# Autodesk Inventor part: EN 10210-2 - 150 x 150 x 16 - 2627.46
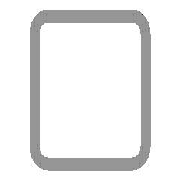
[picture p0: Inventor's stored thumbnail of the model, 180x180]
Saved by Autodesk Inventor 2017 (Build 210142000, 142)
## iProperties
Created: 2016-02
Part Number: EN 10210-2 - 150 x 150 x 16 - 2627.46
Material: Steel, Mild
Description: Tube
Document SubType Name: Modeling
Standard: DIN
Designer: iusti
Standard Revision: 2006-07
Standards Organization: DIN
Language: en-US
Size Designation: 150 x 150 x 16
Categories: <MemberInstance><Categories><Category DisplayName="Structural Shapes" InternalName="089c4875-fa83-4c05-b084-43b9cc11f5ed" Mnemonic="GRDR"><CategoryParameter Dis
Stock Number: 150 x 150 x 16
Density: 7.85 g/cm^3
Appearance: Semi-Polished
IsCustomPart: 1
_CCFamilyMember: 70
_CCFamilyDisplayName: DIN EN 10210-2 (Square) - Tube — Sizes in parentheses have been withdrawn
_FrameMemberDoc: Frame Member File
_Version: 15.0.0
_GetPNFromCC: 1
Author: iusti
G_L: 2627.460 mm
G_W: 150.000 mm
G_H: 150.000 mm
+AC2412DF-FBE4-4A06-B88A-D7E3DE0B8CAC+CUTDETAIL1: Cut
+05A7F50A-9806-4571-A7E4-6AEFE63C232C+CUTDETAIL2: Cut
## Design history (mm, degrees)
node "Start plane"
node "End plane"
sketch "Sketch"
  geometry: L1 (-75, -51)-(-75, 51); L2 (-51, 75)-(51, 75); L3 (75, 51)-(75, -51); L4 (51, -75)-(-51, -75); L5 (-43, 59)-(43, 59); L6 (59, 43)-(59, -43); L7 (43, -59)-(-43, -59); L8 (-59, -43)-(-59, 43); L9 (0, 111.959)-(0, -111.959) reference; L10 (-111.959, 0)-(111.959, 0) reference; A1 r 24 centre (-51, -51) between (-75, -51) and (-51, -75); A2 r 24 centre (-51, 51) between (-51, 75) and (-75, 51); A3 r 24 centre (51, 51) between (75, 51) and (51, 75); A4 r 24 centre (51, -51) between (51, -75) and (75, -51); A5 r 16 centre (-43, -43) between (-59, -43) and (-43, -59); A6 r 16 centre (-43, 43) between (-43, 59) and (-59, 43); A7 r 16 centre (43, 43) between (59, 43) and (43, 59); A8 r 16 centre (43, -43) between (43, -59) and (59, -43)
  constraints: 16 end point, 16 point on circle, 16 tangent, 8 centre point, 6 equal radius, 4 parallel, 2 perpendicular, 2 other
  dimensions: "d7" = 24 radius of A1 (= G_IR); "d10" = 150 distance between parallel lines of L2 L4 (= G_H); "d11" = 150 distance between parallel lines of L1 L3 (= G_W); "d12" = 16 distance between parallel lines of L3 L6 (= G_T); "d15" = 75 distance between parallel lines of L2 L10 (= 0.5 x d10); "d16" = 75 distance between parallel lines of L9 L3 (= 0.5 x d11); "d19" = 16 radius of A5 (= G_T); "d20" = 16 distance between parallel lines of L4 L7 (= G_T)
extrude "Body" new body sketch "Sketch" stored distance "d3" = 2627.46034 (= G_L); taper "d4" = 0 deg
node "Driven Length"
  sketch "Sketch3"
    geometry: L1 (0, 0)-(10, 0) reference
    constraints: 2 end point, 1 horizontal
  workplane "Work Plane3"
  sketch "Sketch4"
    geometry: L1 (-2, 35.842)-(12, 35.842) reference; L2 (-2, 2663.303)-(12, 2663.303) reference
    dimensions: "d18" = 2627.46034 distance between parallel lines of L1 L2 (derived)
workplane "Work Plane4"
split "Split1"
workplane "Work Plane5"
split "Split2"
body "Solid1"
other parameters: "G_W" = 150 [user parameter; used in 1 equation term], "G_H" = 150 [user parameter; used in 1 equation term], "G_T" = 16 [user parameter; used in 3 equation terms], "G_IR" = 24 [user parameter; used in 1 equation term], "G_L" = 2627.46034 (= d18) [user parameter; used in 1 equation term], "G_OFFSET_START" = -35.84222 [user parameter; used in 1 equation term], "G_OFFSET_END" = 92.90179 [user parameter; used in 1 equation term], "d13" = 35.84222 (= -G_OFFSET_START), "d14" = 2663.30256 (= G_OFFSET_END + B_L), "B_L" = 2570.40077 [user parameter; used in 1 equation term], "d17" = 90 deg
